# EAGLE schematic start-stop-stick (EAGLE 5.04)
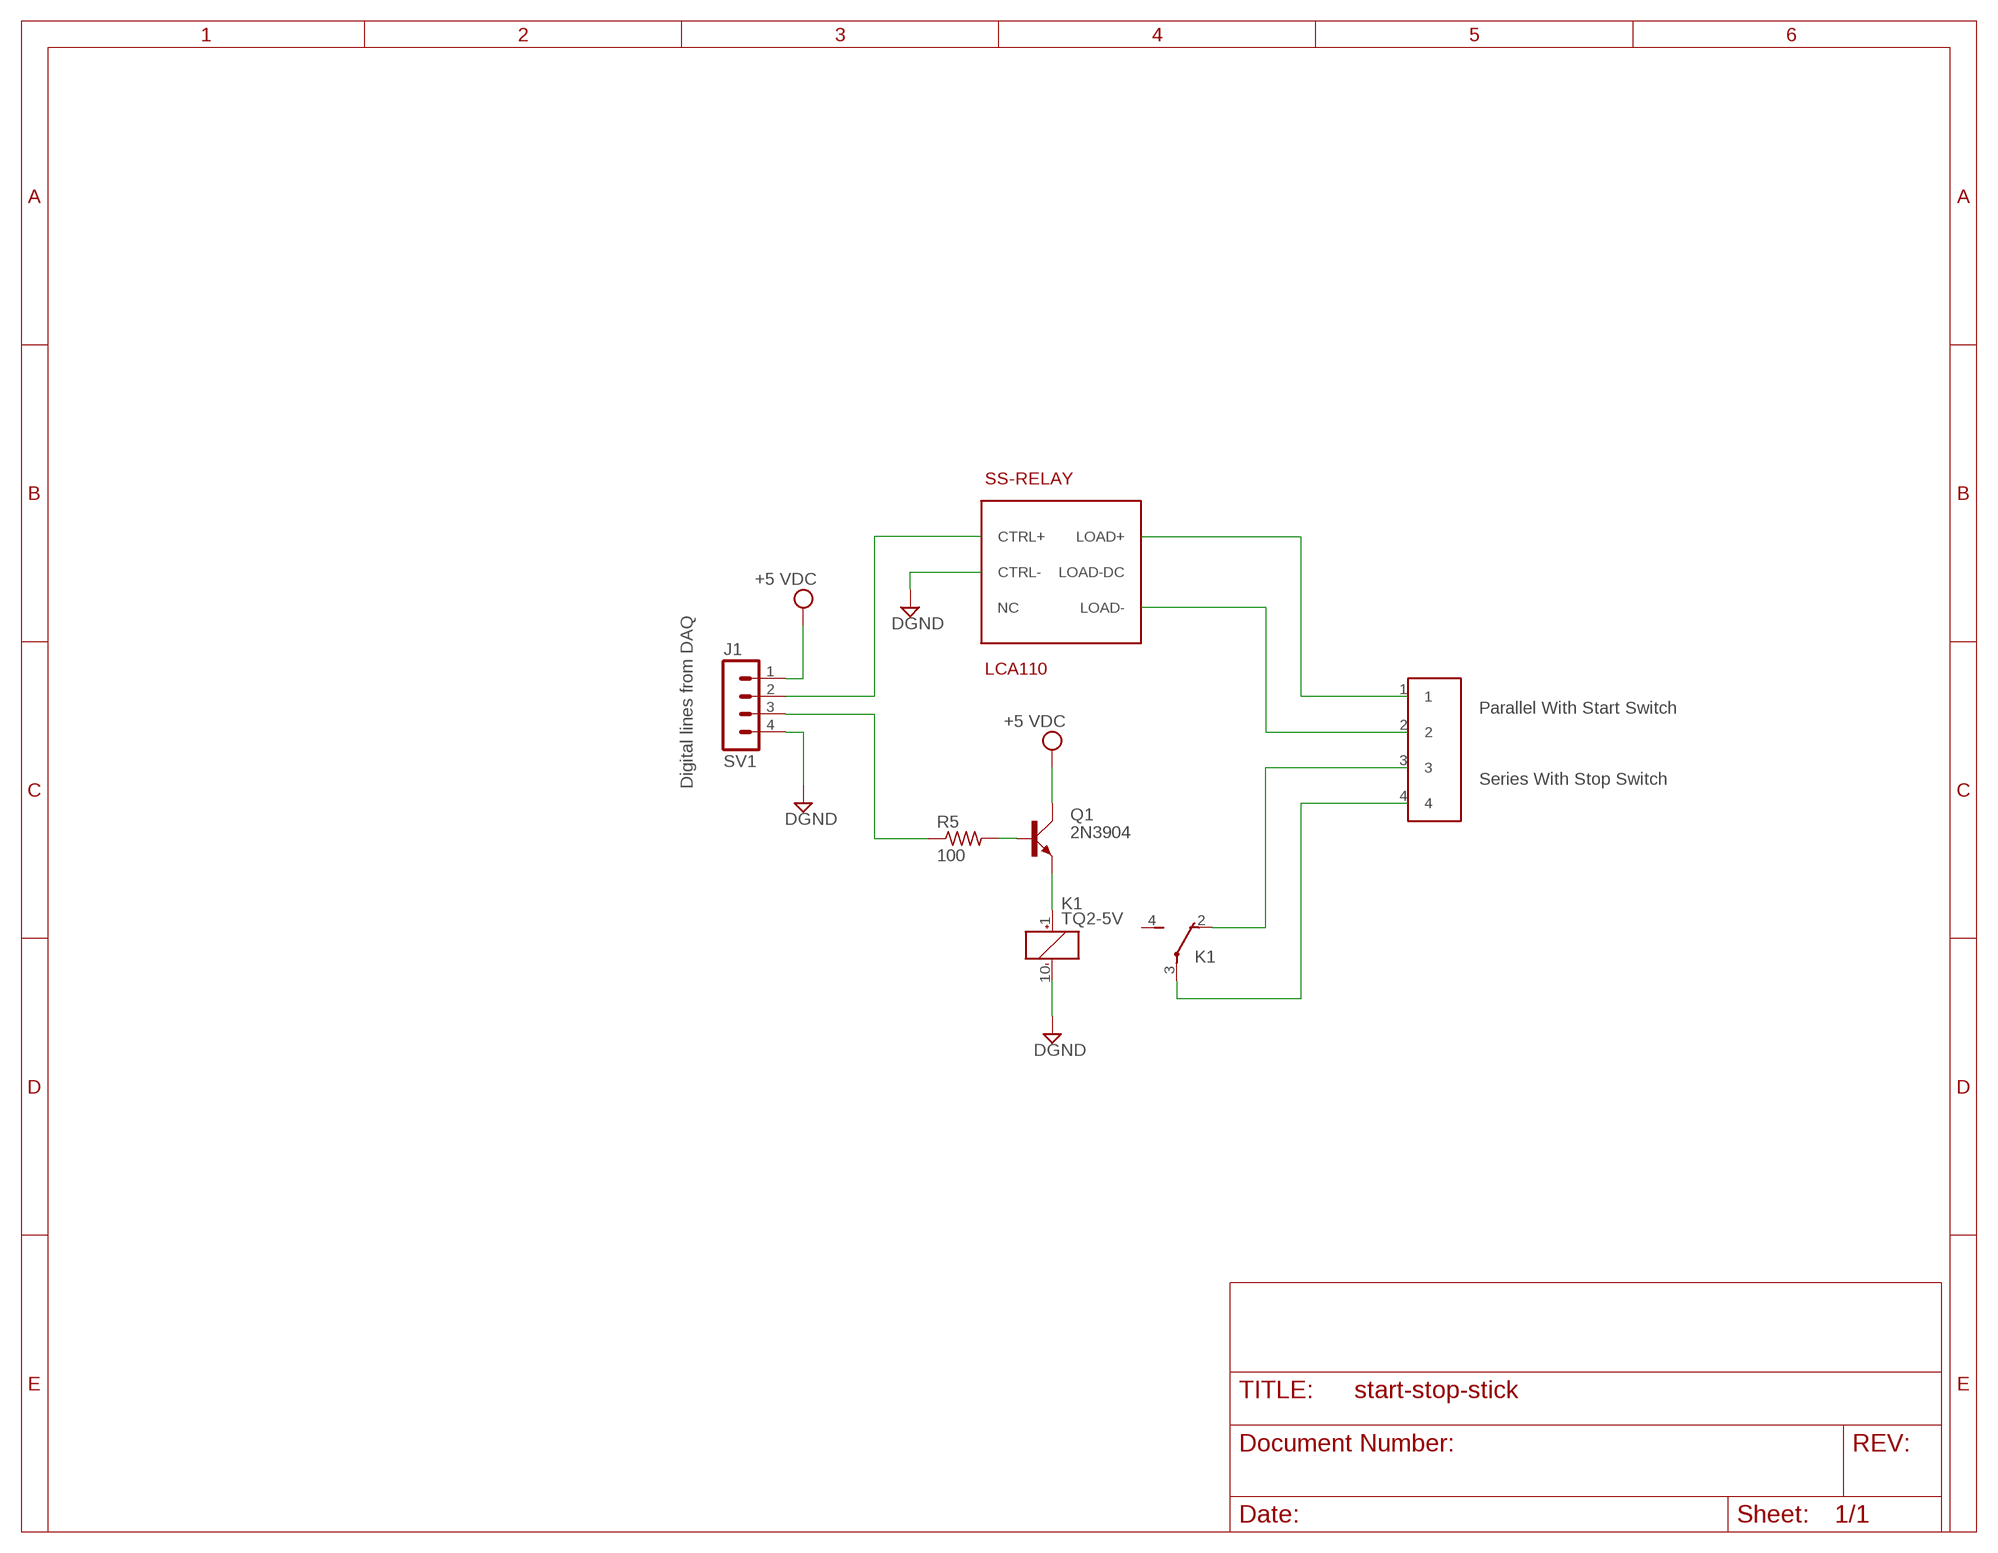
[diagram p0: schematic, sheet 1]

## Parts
K1  TQ2-5V  [TQ2]
Q1  2N3904  [TO92D]
R5  100  R-US_0204/5  [0204/5]
SS-RELAY  LCA110  [6DIP]
SV1  J1  MA04-1  [MA04-1]
U$1  POWER4B  [POWER4]

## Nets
AGND: K1.10(_:-) SS-RELAY.P$2(CTRL-) SV1.4 ; supply symbol labelled DGND
N$1: K1.2(1:O) U$1.3
N$2: K1.3(1:P) U$1.4
N$3: K1.1(_:+) Q1.E
N$4: Q1.B R5.2
N$5: SS-RELAY.P$4(LOAD-) U$1.2
N$6: SS-RELAY.P$6(LOAD+) U$1.1
N$8: SS-RELAY.P$1(CTRL+) SV1.2
N$9: R5.1 SV1.3
VCC: Q1.C SV1.1 ; supply symbol labelled +5 VDC
Unconnected: K1.4(1:S) K1.7(2:S) K1.8(2:P) K1.9(2:O) SS-RELAY.P$3(NC) SS-RELAY.P$5(LOAD-DC)

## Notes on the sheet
- Parallel With Start Switch
- Digital lines from DAQ | Series With Stop Switch

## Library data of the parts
K1 = relay:TQ2?*: LOW PROFILE 2 FORM C RELAY NAiS Source: http://www.mew-europe.com/.. en_ds_61020_0001.pdf Source: http://www.mew-europe.com/.. en_ds_61020_0004.pdf
Q1 = transistor-small-signal:2N3904: NPN TRANSISTOR
R5 = resistor:R-US_: RESISTOR, American symbol
SS-RELAY = trl:LCA110
SV1 = con-lstb:MA04-1: PIN HEADER
U$1 = trl:POWER4B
